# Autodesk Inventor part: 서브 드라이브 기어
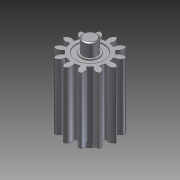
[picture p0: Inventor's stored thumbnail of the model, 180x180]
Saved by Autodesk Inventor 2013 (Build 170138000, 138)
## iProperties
Created: 2013-07
Part Number: 서브 드라이브 기어
Document SubType Name: Modeling
Designer: 한국산업디자인학원
Density: 1 g/cm^3
Mass: 123.501 g
Surface Area: 265.416 cm^2
Volume: 123.501 cm^3
Material: 강철, 탄소
변환 표준: STEP AP214IS
파일 이름: C:\Documents and Settings\?댁씪諛곗?1\諛뷀깢 ?붾㈃\2013-07-27 ?덉긽臾몄젣\媛?몄삩 援ъ꽦?붿냼\留ㅺ컻蹂??MZ)?섏젙?섎㈃ ?먮룞? 留뚮뱾?댁????ㅽ띁湲곗뼱.stp
전처리기: Build: 223b, Release: 2010 RTM - Date: Sat 02/14/2009
전송 단위: 밀리미터
불확실성: 0.01
Author: 한국산업디자인학원
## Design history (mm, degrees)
sketch "스케치1"
  geometry: A1 r 6 centre (-2.816, 23.011) between (2.462, 20.157) and (0.524, 27.995) reference; A2 r 28 centre (0, 0) between (0.524, 27.995) and (-0.524, 27.995) reference; A3 r 6 centre (2.816, 23.011) between (-0.524, 27.995) and (-2.462, 20.157) reference; A4 r 0.972 centre (-3.318, 19.695) between (-3.156, 18.736) and (-2.462, 20.157) reference; A5 r 19 centre (0, 0) between (-3.156, 18.736) and (-6.635, 17.804) reference; A6 r 0.972 centre (-6.974, 18.715) between (-7.946, 18.688) and (-6.635, 17.804) reference; A7 r 6 centre (-13.944, 18.52) between (-7.946, 18.688) and (-13.544, 24.506) reference; A8 r 28 centre (0, 0) between (-13.544, 24.506) and (-14.451, 23.983) reference; A9 r 6 centre (-9.067, 21.336) between (-14.451, 23.983) and (-12.211, 16.226) reference; A10 r 0.972 centre (-12.721, 15.397) between (-12.101, 14.648) and (-12.211, 16.226) reference; A11 r 19 centre (0, 0) between (-12.101, 14.648) and (-14.648, 12.101) reference; A12 r 0.972 centre (-15.397, 12.721) between (-16.226, 12.211) and (-14.648, 12.101) reference; A13 r 6 centre (-21.336, 9.067) between (-16.226, 12.211) and (-23.983, 14.451) reference; A14 r 28 centre (0, 0) between (-23.983, 14.451) and (-24.506, 13.544) reference; A15 r 6 centre (-18.52, 13.944) between (-24.506, 13.544) and (-18.688, 7.946) reference; A16 r 0.972 centre (-18.715, 6.974) between (-17.804, 6.635) and (-18.688, 7.946) reference; A17 r 19 centre (0, 0) between (-17.804, 6.635) and (-18.736, 3.156) reference; A18 r 0.972 centre (-19.695, 3.318) between (-20.157, 2.462) and (-18.736, 3.156) reference; A19 r 6 centre (-23.011, -2.816) between (-20.157, 2.462) and (-27.995, 0.524) reference; A20 r 28 centre (0, 0) between (-27.995, 0.524) and (-27.995, -0.524) reference; A21 r 6 centre (-23.011, 2.816) between (-27.995, -0.524) and (-20.157, -2.462) reference; A22 r 0.972 centre (-19.695, -3.318) between (-18.736, -3.156) and (-20.157, -2.462) reference; A23 r 19 centre (0, 0) between (-18.736, -3.156) and (-17.804, -6.635) reference; A24 r 0.972 centre (-18.715, -6.974) between (-18.688, -7.946) and (-17.804, -6.635) reference; A25 r 6 centre (-18.52, -13.944) between (-18.688, -7.946) and (-24.506, -13.544) reference; A26 r 28 centre (0, 0) between (-24.506, -13.544) and (-23.983, -14.451) reference; A27 r 6 centre (-21.336, -9.067) between (-23.983, -14.451) and (-16.226, -12.211) reference; A28 r 0.972 centre (-15.397, -12.721) between (-14.648, -12.101) and (-16.226, -12.211) reference; A29 r 19 centre (0, 0) between (-14.648, -12.101) and (-12.101, -14.648) reference; A30 r 0.972 centre (-12.721, -15.397) between (-12.211, -16.226) and (-12.101, -14.648) reference; A31 r 6 centre (-9.067, -21.336) between (-12.211, -16.226) and (-14.451, -23.983) reference; A32 r 28 centre (0, 0) between (-14.451, -23.983) and (-13.544, -24.506) reference; A33 r 6 centre (-13.944, -18.52) between (-13.544, -24.506) and (-7.946, -18.688) reference; A34 r 0.972 centre (-6.974, -18.715) between (-6.635, -17.804) and (-7.946, -18.688) reference; A35 r 19 centre (0, 0) between (-6.635, -17.804) and (-3.156, -18.736) reference; A36 r 0.972 centre (-3.318, -19.695) between (-2.462, -20.157) and (-3.156, -18.736) reference; A37 r 6 centre (2.816, -23.011) between (-2.462, -20.157) and (-0.524, -27.995) reference; A38 r 28 centre (0, 0) between (-0.524, -27.995) and (0.524, -27.995) reference; A39 r 6 centre (-2.816, -23.011) between (0.524, -27.995) and (2.462, -20.157) reference; A40 r 0.972 centre (3.318, -19.695) between (3.156, -18.736) and (2.462, -20.157) reference; A41 r 19 centre (0, 0) between (3.156, -18.736) and (6.635, -17.804) reference; A42 r 0.972 centre (6.974, -18.715) between (7.946, -18.688) and (6.635, -17.804) reference; A43 r 6 centre (13.944, -18.52) between (7.946, -18.688) and (13.544, -24.506) reference; A44 r 28 centre (0, 0) between (13.544, -24.506) and (14.451, -23.983) reference; A45 r 6 centre (9.067, -21.336) between (14.451, -23.983) and (12.211, -16.226) reference; A46 r 0.972 centre (12.721, -15.397) between (12.101, -14.648) and (12.211, -16.226) reference; A47 r 19 centre (0, 0) between (12.101, -14.648) and (14.648, -12.101) reference; A48 r 0.972 centre (15.397, -12.721) between (16.226, -12.211) and (14.648, -12.101) reference; A49 r 6 centre (21.336, -9.067) between (16.226, -12.211) and (23.983, -14.451) reference; A50 r 28 centre (0, 0) between (23.983, -14.451) and (24.506, -13.544) reference; A51 r 6 centre (18.52, -13.944) between (24.506, -13.544) and (18.688, -7.946) reference; A52 r 0.972 centre (18.715, -6.974) between (17.804, -6.635) and (18.688, -7.946) reference; A53 r 19 centre (0, 0) between (17.804, -6.635) and (18.736, -3.156) reference; A54 r 0.972 centre (19.695, -3.318) between (20.157, -2.462) and (18.736, -3.156) reference; A55 r 6 centre (23.011, 2.816) between (20.157, -2.462) and (27.995, -0.524) reference; A56 r 28 centre (0, 0) between (27.995, -0.524) and (27.995, 0.524) reference; A57 r 6 centre (23.011, -2.816) between (27.995, 0.524) and (20.157, 2.462) reference; A58 r 0.972 centre (19.695, 3.318) between (18.736, 3.156) and (20.157, 2.462) reference; A59 r 19 centre (0, 0) between (18.736, 3.156) and (17.804, 6.635) reference; A60 r 0.972 centre (18.715, 6.974) between (18.688, 7.946) and (17.804, 6.635) reference; A61 r 6 centre (18.52, 13.944) between (18.688, 7.946) and (24.506, 13.544) reference; A62 r 28 centre (0, 0) between (24.506, 13.544) and (23.983, 14.451) reference; A63 r 6 centre (21.336, 9.067) between (23.983, 14.451) and (16.226, 12.211) reference; A64 r 0.972 centre (15.397, 12.721) between (14.648, 12.101) and (16.226, 12.211) reference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; 1 further point
extrude "돌출1" new body sketch "스케치1" stored distance "d0" = 70; taper "d1" = 0 deg
sketch "스케치2"
  geometry: C1 r 7.5 at (0, 0); 1 further point
  constraints: 1 centre point, 1 coincident
  dimensions: "d2" = 15 diameter of C1
extrude "돌출2" join sketch "스케치2" distance "d3" = 14; taper "d4" = 0 deg
chamfer "모따기1" distance "d5" = 1; stored, may be unused: second distance "d6" = 2, angle "d7" = 45 deg
node "작업 평면1"
sketch "스케치3"
  geometry: C1 r 9.5 at (0, 0); C2 r 15 at (0, 0); 1 further point
  constraints: 2 centre point, 2 coincident
  dimensions: "d8" = 19 diameter of C1; "d9" = 30 diameter of C2
extrude "돌출3" cut sketch "스케치3" distance "d10" = 1; taper "d11" = 0 deg
node "솔리드4"
mirror "대칭1"
mirror "대칭2"
node "투영된 루프1"
node "솔리드2"
